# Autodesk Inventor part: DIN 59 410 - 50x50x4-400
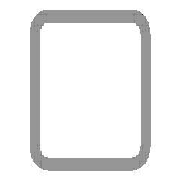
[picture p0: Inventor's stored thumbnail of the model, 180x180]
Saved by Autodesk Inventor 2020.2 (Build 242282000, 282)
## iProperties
Manager: www.cadconsulting.pl
Company: Fabian Stasiak CAD Consulting
Created: 2015-01
Part Number: DIN 59 410 - 50x50x4-400
Material: Stal, miękka
Description: Rurki stalowe o przekroju kwadratowym formowane na gorąco
Document SubType Name: Modellieren
Standard: DIN
Designer: F.Stasiak
Standards Organization: DIN
Language: pl-PL
Size Designation: 50x50x4
Categories: <MemberInstance><Categories><Category DisplayName="Kształtowniki konstrukcyjne" InternalName="089c4875-fa83-4c05-b084-43b9cc11f5ed" Mnemonic="GRDR"><CategoryPar
Stock Number: 50x50x4
Density: 7.85 g/cm^3
Appearance: Częściowo polerowana
Mass: 2181.66 g
Surface Area: 1403.49 cm^2
Volume: 277.919 cm^3
Catalog Web Link: www.expertbooks.pl
_CCFamilyMember: 40
_CCFamilyDisplayName: DIN 59410 (Kwadrat) - Rurki stalowe o przekroju kwadratowym formowane na gorąco
_FrameMemberDoc: Frame Member File
_Version: 15.0.0
_GetPNFromCC: 1
G_W: 50,000 mm
G_H: 50,000 mm
+A60D2A78-D74A-48A7-A341-AC7013FCE6D6+CUTDETAIL1: Wytnij
+45B7BE0C-E2C9-444F-9274-919045130A66+CUTDETAIL2: Wytnij
G_L: 400,000 mm
IsCustomPart: 1
Author: F.Stasiak
Subject: Zbiór ćwiczeń. Autodesk Inventor 2020. Kurs Professional
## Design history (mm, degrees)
node "Płaszczyzna początkowa"
node "Płaszczyzna końcowa"
sketch "Szkic"
  geometry: L1 (-17, 25)-(17, 25); L2 (25, 17)-(25, -17); L3 (17, -25)-(-17, -25); L4 (-25, -17)-(-25, 17); L5 (-37.32, 0)-(37.32, 0) reference; L6 (0, -37.32)-(0, 37.32) reference; L7 (-17, 21)-(17, 21); L8 (21, 17)-(21, -17); L9 (17, -21)-(-17, -21); L10 (-21, -17)-(-21, 17); A1 r 8 centre (-17, 17) between (-17, 25) and (-25, 17); A2 r 8 centre (17, 17) between (25, 17) and (17, 25); A3 r 8 centre (17, -17) between (17, -25) and (25, -17); A4 r 8 centre (-17, -17) between (-25, -17) and (-17, -25); A5 r 4 centre (-17, 17) between (-17, 21) and (-21, 17); A6 r 4 centre (17, 17) between (21, 17) and (17, 21); A7 r 4 centre (17, -17) between (17, -21) and (21, -17); A8 r 4 centre (-17, -17) between (-21, -17) and (-17, -21); 3 further points
  constraints: 16 end point, 16 point on circle, 8 centre point, 8 tangent, 6 point on line, 4 parallel, 3 equal radius, 3 perpendicular, 1 horizontal, 7 other
  dimensions: "b" = 50 distance of point (-25, 25) point (25, 25); "msp_r" = 8 radius of A1 (= 2 x ParT); "d8" = 25 distance between parallel lines of L4 L6 (= d9); "d9" = 25 distance between parallel lines of L3 L5 (= 0.5 x b); "d10" = 4 distance between parallel lines of L3 L9 (= ParT)
extrude "Bryła" new body sketch "Szkic" taper "d4" = 0 deg; stored distance "NLG" = 10
node "Driven Length"
  sketch "Sketch2"
    geometry: L1 (0, 0)-(10, 0) reference
    constraints: 2 end point, 1 horizontal
  workplane "Work Plane3"
  sketch "Sketch3"
    geometry: L1 (-2, 25)-(12, 25) reference; L2 (-2, 425)-(12, 425) reference
    dimensions: "d14" = 400 distance between parallel lines of L1 L2 (derived)
node "Płaszczyzna konstrukcyjna4"
feature "Podział1"
node "Płaszczyzna konstrukcyjna5"
feature "Podział2"
body "Solid1"
other parameters: "ParT" = 4, "G_OFFSET_START" = -25 [user parameter; used in 1 equation term], "G_OFFSET_END" = -25 [user parameter; used in 1 equation term], "d11" = 25 (= -G_OFFSET_START), "d12" = 425 (= G_OFFSET_END + B_L), "G_L" = 400 (= d14) [user parameter], "d13" = 90 deg
